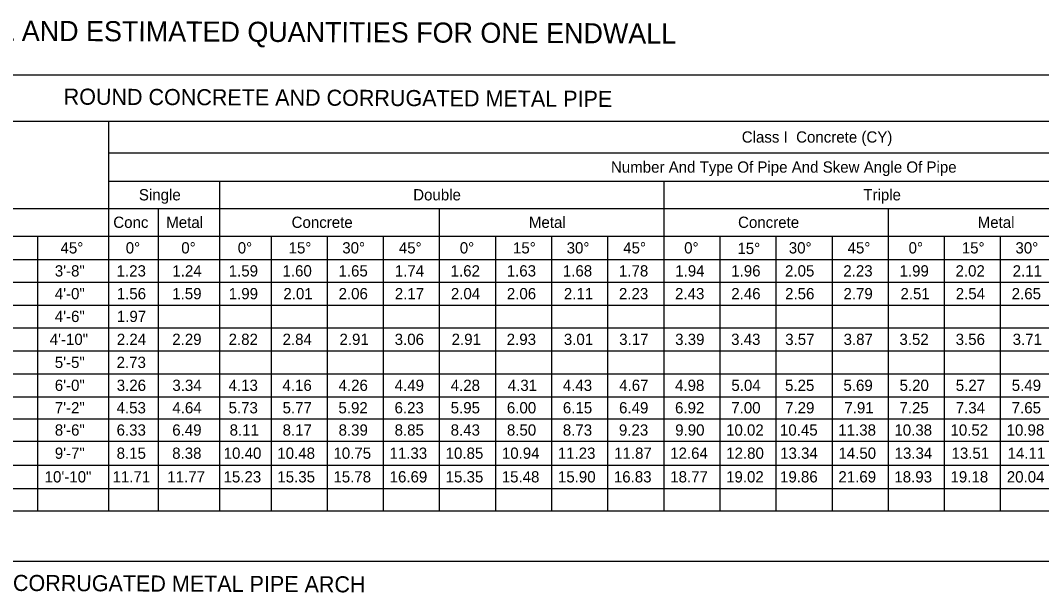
# Model space of a CAD drawing. Extents: x 10029 to 10796, y 10063 to 10519.
# Drawn here: x 10299.4 to 10616.8, y 10341.1 to 10518.9 of the extents above; entities that cross this region are included whole.
import ezdxf

# ---------------------------------------------------------------- set-up
doc = ezdxf.new("R2010")
doc.units = 0
doc.layers.add('Default', color=7, linetype='Continuous')
doc.layers.add('Dimension', color=7, linetype='Continuous')

msp = doc.modelspace()

# ---------------------------------------------------------------- linework, layer by layer
at = {"layer": 'Default'}
for p, q in [((10028.97, 10502.01), (10795.89, 10502.01)), ((10028.97, 10487.65), (10795.89, 10487.65)), ((10326.86, 10366.47), (10326.86, 10487.65)), ((10326.86, 10477.72), (10783.03, 10477.72)), ((10326.86, 10468.97), (10783.03, 10468.97)), ((10361.4, 10366.47), (10361.4, 10468.97)), ((10499.44, 10366.47), (10499.44, 10468.97)), ((10042.36, 10460.49), (10783.03, 10460.49)), ((10342.27, 10366.47), (10342.27, 10460.49)), ((10429.69, 10366.47), (10429.69, 10460.49)), ((10569.19, 10366.47), (10569.19, 10460.49)), ((10244.78, 10451.88), (10783.03, 10451.88)), ((10304.74, 10366.47), (10304.74, 10451.88)), ((10377.37, 10366.47), (10377.37, 10451.88)), ((10394.81, 10366.47), (10394.81, 10451.88)), ((10412.25, 10366.47), (10412.25, 10451.88)), ((10447.13, 10366.47), (10447.13, 10451.88)), ((10464.57, 10366.47), (10464.57, 10451.88)), ((10482, 10366.47), (10482, 10451.88)), ((10516.88, 10366.47), (10516.88, 10451.88)), ((10534.32, 10366.47), (10534.32, 10451.88)), ((10551.76, 10366.47), (10551.76, 10451.88)), ((10586.63, 10366.47), (10586.63, 10451.88)), ((10604.07, 10366.47), (10604.07, 10451.88)), ((10028.97, 10444.58), (10795.89, 10444.58)), ((10028.97, 10437.55), (10795.89, 10437.55)), ((10028.97, 10430.43), (10795.89, 10430.43)), ((10028.97, 10423.41), (10795.89, 10423.41)), ((10028.97, 10416.18), (10795.89, 10416.18)), ((10028.97, 10409.08), (10795.89, 10409.08)), ((10028.97, 10401.92), (10795.89, 10401.92)), ((10028.97, 10395.12), (10795.89, 10395.12)), ((10028.97, 10388.08), (10795.89, 10388.08)), ((10028.97, 10380.7), (10795.89, 10380.7)), ((10028.97, 10373.4), (10795.89, 10373.4)), ((10028.97, 10366.47), (10795.89, 10366.47)), ((10039.72, 10350.86), (10681.45, 10350.86))]:
    msp.add_line(p, q, dxfattribs=at)

# ---------------------------------------------------------------- texts
at = {"layer": 'Dimension'}
for s, height, rotation, p in [('DATA AND ESTIMATED QUANTITIES FOR ONE ENDWALL', 6.25, 359.7555, (10275.18, 10512.68)), ('ROUND CONCRETE AND CORRUGATED METAL PIPE', 5, 359.7555, (10312.81, 10492.75)), ('3\'-8"', 3.5, 0, (10310.06, 10439.32)), ('1.23', 3.5, 0, (10329.27, 10439.32)), ('1.24', 3.5, 0, (10346.6, 10439.32)), ('1.59', 3.5, 0, (10364.12, 10439.32)), ('1.60', 3.5, 0, (10380.84, 10439.32)), ('1.65', 3.5, 0, (10398.25, 10439.32)), ('1.74', 3.5, 0, (10415.74, 10439.32)), ('1.62', 3.5, 0, (10433.11, 10439.32)), ('1.63', 3.5, 0, (10450.54, 10439.32)), ('1.68', 3.5, 0, (10467.99, 10439.32)), ('1.78', 3.5, 0, (10485.43, 10439.32)), ('1.94', 3.5, 0, (10502.93, 10439.32)), ('1.96', 3.5, 0, (10520.34, 10439.32)), ('2.05', 3.5, 0, (10537.05, 10439.32)), ('2.23', 3.5, 0, (10555.17, 10439.32)), ('1.99', 3.5, 0, (10572.65, 10439.32)), ('2.02', 3.5, 0, (10590.05, 10439.32)), ('2.11', 3.5, 0, (10607.81, 10439.32)), ('4\'-0"', 3.5, 0, (10310.06, 10432.24)), ('1.56', 3.5, 0, (10329.31, 10432.24)), ('1.59', 3.5, 0, (10346.57, 10432.24)), ('1.99', 3.5, 0, (10364.12, 10432.24)), ('2.01', 3.5, 0, (10381.11, 10432.24)), ('2.06', 3.5, 0, (10398.27, 10432.24)), ('2.17', 3.5, 0, (10415.75, 10432.24)), ('2.04', 3.5, 0, (10433.18, 10432.24)), ('2.06', 3.5, 0, (10450.58, 10432.24)), ('2.11', 3.5, 0, (10468.3, 10432.24)), ('2.23', 3.5, 0, (10485.42, 10432.24)), ('2.43', 3.5, 0, (10502.86, 10432.24)), ('2.46', 3.5, 0, (10520.34, 10432.24)), ('2.56', 3.5, 0, (10537.07, 10432.24)), ('2.79', 3.5, 0, (10555.21, 10432.24)), ('2.51', 3.5, 0, (10572.93, 10432.24)), ('2.54', 3.5, 0, (10590.12, 10432.24)), ('2.65', 3.5, 0, (10607.51, 10432.24)), ('4\'-6"', 3.5, 0, (10310.06, 10425.17)), ('1.97', 3.5, 0, (10329.35, 10425.17)), ('4\'-10"', 3.5, 0, (10308.48, 10418.04)), ('2.24', 3.5, 0, (10329.34, 10418.04)), ('2.29', 3.5, 0, (10346.57, 10418.04)), ('2.82', 3.5, 0, (10364.09, 10418.04)), ('2.84', 3.5, 0, (10380.86, 10418.04)), ('2.91', 3.5, 0, (10398.55, 10418.04)), ('3.06', 3.5, 0, (10415.71, 10418.04)), ('2.91', 3.5, 0, (10433.42, 10418.04)), ('2.93', 3.5, 0, (10450.54, 10418.04)), ('3.01', 3.5, 0, (10468.3, 10418.04)), ('3.17', 3.5, 0, (10485.5, 10418.04)), ('3.39', 3.5, 0, (10502.9, 10418.04)), ('3.43', 3.5, 0, (10520.3, 10418.04)), ('3.57', 3.5, 0, (10537.11, 10418.04)), ('3.87', 3.5, 0, (10555.26, 10418.04)), ('3.52', 3.5, 0, (10572.61, 10418.04)), ('3.56', 3.5, 0, (10590.09, 10418.04)), ('3.71', 3.5, 0, (10607.81, 10418.04)), ('5\'-5"', 3.5, 0, (10310.06, 10410.88)), ('2.73', 3.5, 0, (10329.27, 10410.88)), ('6\'-0"', 3.5, 0, (10310.06, 10403.75)), ('3.26', 3.5, 0, (10329.31, 10403.75)), ('3.34', 3.5, 0, (10346.6, 10403.75)), ('4.13', 3.5, 0, (10364.08, 10403.75)), ('4.16', 3.5, 0, (10380.83, 10403.75)), ('4.26', 3.5, 0, (10398.27, 10403.75)), ('4.49', 3.5, 0, (10415.71, 10403.75)), ('4.28', 3.5, 0, (10433.12, 10403.75)), ('4.31', 3.5, 0, (10450.86, 10403.75)), ('4.43', 3.5, 0, (10467.98, 10403.75)), ('4.67', 3.5, 0, (10485.5, 10403.75)), ('4.98', 3.5, 0, (10502.87, 10403.75)), ('5.04', 3.5, 0, (10520.37, 10403.75)), ('5.25', 3.5, 0, (10537.05, 10403.75)), ('5.69', 3.5, 0, (10555.21, 10403.75)), ('5.20', 3.5, 0, (10572.66, 10403.75)), ('5.27', 3.5, 0, (10590.13, 10403.75)), ('5.49', 3.5, 0, (10607.53, 10403.75)), ('7\'-2"', 3.5, 0, (10310.06, 10396.77)), ('4.53', 3.5, 0, (10329.27, 10396.77)), ('4.64', 3.5, 0, (10346.6, 10396.77)), ('5.73', 3.5, 0, (10364.08, 10396.77)), ('5.77', 3.5, 0, (10380.87, 10396.77)), ('5.92', 3.5, 0, (10398.23, 10396.77)), ('6.23', 3.5, 0, (10415.67, 10396.77)), ('5.95', 3.5, 0, (10433.12, 10396.77)), ('6.00', 3.5, 0, (10450.59, 10396.77)), ('6.15', 3.5, 0, (10468, 10396.77)), ('6.49', 3.5, 0, (10485.46, 10396.77)), ('6.92', 3.5, 0, (10502.86, 10396.77)), ('7.00', 3.5, 0, (10520.34, 10396.77)), ('7.29', 3.5, 0, (10537.07, 10396.77)), ('7.91', 3.5, 0, (10555.49, 10396.77)), ('7.25', 3.5, 0, (10572.63, 10396.77)), ('7.34', 3.5, 0, (10590.12, 10396.77)), ('7.65', 3.5, 0, (10607.51, 10396.77)), ('8\'-6"', 3.5, 0, (10310.06, 10389.85)), ('6.33', 3.5, 0, (10329.27, 10389.85)), ('6.49', 3.5, 0, (10346.57, 10389.85)), ('8.11', 3.5, 0, (10364.4, 10389.85)), ('8.17', 3.5, 0, (10380.87, 10389.85)), ('8.39', 3.5, 0, (10398.27, 10389.85)), ('8.85', 3.5, 0, (10415.68, 10389.85)), ('8.50', 3.5, 0, (10450.59, 10389.85)), ('8.73', 3.5, 0, (10467.98, 10389.85)), ('9.23', 3.5, 0, (10485.42, 10389.85)), ('9.90', 3.5, 0, (10502.91, 10389.85)), ('10.02', 3.5, 0, (10518.73, 10389.85)), ('10.45', 3.5, 0, (10535.48, 10389.85)), ('11.38', 3.5, 0, (10553.61, 10389.85)), ('10.38', 3.5, 0, (10571.05, 10389.85)), ('10.52', 3.5, 0, (10588.48, 10389.85)), ('10.98', 3.5, 0, (10605.93, 10389.85)), ('9\'-7"', 3.5, 0, (10310.06, 10382.64)), ('8.15', 3.5, 0, (10329.28, 10382.64)), ('8.38', 3.5, 0, (10346.55, 10382.64)), ('10.40', 3.5, 0, (10362.56, 10382.64)), ('10.48', 3.5, 0, (10379.23, 10382.64)), ('10.75', 3.5, 0, (10396.67, 10382.64)), ('11.33', 3.5, 0, (10414.1, 10382.64)), ('10.85', 3.5, 0, (10431.55, 10382.64)), ('10.94', 3.5, 0, (10449.04, 10382.64)), ('11.23', 3.5, 0, (10466.41, 10382.64)), ('11.87', 3.5, 0, (10483.93, 10382.64)), ('12.64', 3.5, 0, (10501.36, 10382.64)), ('12.80', 3.5, 0, (10518.77, 10382.64)), ('13.34', 3.5, 0, (10535.53, 10382.64)), ('14.50', 3.5, 0, (10553.65, 10382.64)), ('13.34', 3.5, 0, (10571.11, 10382.64)), ('13.51', 3.5, 0, (10588.8, 10382.64)), ('14.11', 3.5, 0, (10606.23, 10382.64)), ('10\'-10"', 3.5, 0, (10306.91, 10375.3)), ('11.71', 3.5, 0, (10328.01, 10375.3)), ('11.77', 3.5, 0, (10345.04, 10375.3)), ('15.23', 3.5, 0, (10362.51, 10375.3)), ('15.35', 3.5, 0, (10379.24, 10375.3)), ('15.78', 3.5, 0, (10396.67, 10375.3)), ('18.77', 3.5, 0, (10501.37, 10375.3)), ('19.02', 3.5, 0, (10518.73, 10375.3)), ('19.86', 3.5, 0, (10535.5, 10375.3)), ('21.69', 3.5, 0, (10553.64, 10375.3)), ('CORRUGATED METAL PIPE ARCH', 5, 359.7555, (10297.04, 10341.57))]:
    msp.add_text(s, height=height, rotation=rotation, dxfattribs=at).set_placement(p)
for s, p in [('Class I  Concrete (CY)', (10523.6, 10480.94)), ('Number And Type Of Pipe And Skew Angle Of Pipe', (10482.94, 10471.6)), ('Single', (10336.2, 10462.98)), ('Double', (10421.47, 10462.98)), ('Triple', (10561.38, 10462.98)), ('Conc', (10328.24, 10454.43)), ('Metal', (10344.7, 10454.43)), ('Concrete', (10383.67, 10454.43)), ('Metal', (10457.43, 10454.43)), ('Concrete', (10522.45, 10454.43)), ('Metal', (10596.94, 10454.43)), ('45°', (10311.83, 10446.48)), ('0°', (10332.11, 10446.48)), ('0°', (10349.38, 10446.48)), ('0°', (10366.93, 10446.48)), ('15°', (10382.74, 10446.48)), ('30°', (10399.42, 10446.48)), ('45°', (10417, 10446.48)), ('0°', (10435.95, 10446.48)), ('15°', (10452.49, 10446.48)), ('30°', (10469.17, 10446.48)), ('45°', (10486.75, 10446.48)), ('0°', (10505.7, 10446.48)), ('15°', (10522.25, 10446.3)), ('30°', (10538.22, 10446.48)), ('45°', (10556.5, 10446.48)), ('0°', (10575.46, 10446.48)), ('15°', (10592, 10446.48)), ('30°', (10608.68, 10446.48)), ('8.43', (10433.11, 10389.85)), ('16.69', (10414.14, 10375.3)), ('15.35', (10431.55, 10375.3)), ('15.48', (10448.99, 10375.3)), ('15.90', (10466.46, 10375.3)), ('16.83', (10483.85, 10375.3)), ('18.93', (10571.04, 10375.3)), ('19.18', (10588.49, 10375.3)), ('20.04', (10605.99, 10375.3))]:
    msp.add_text(s, height=3.5, dxfattribs=at).set_placement(p)

doc.saveas('drawing.dxf')
